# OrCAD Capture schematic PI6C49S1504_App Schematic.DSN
size Custom; title: PI6C49S1504 Application Circuit; rev: 1.0; note: Diodes Inc. Clock IC Application Engineering
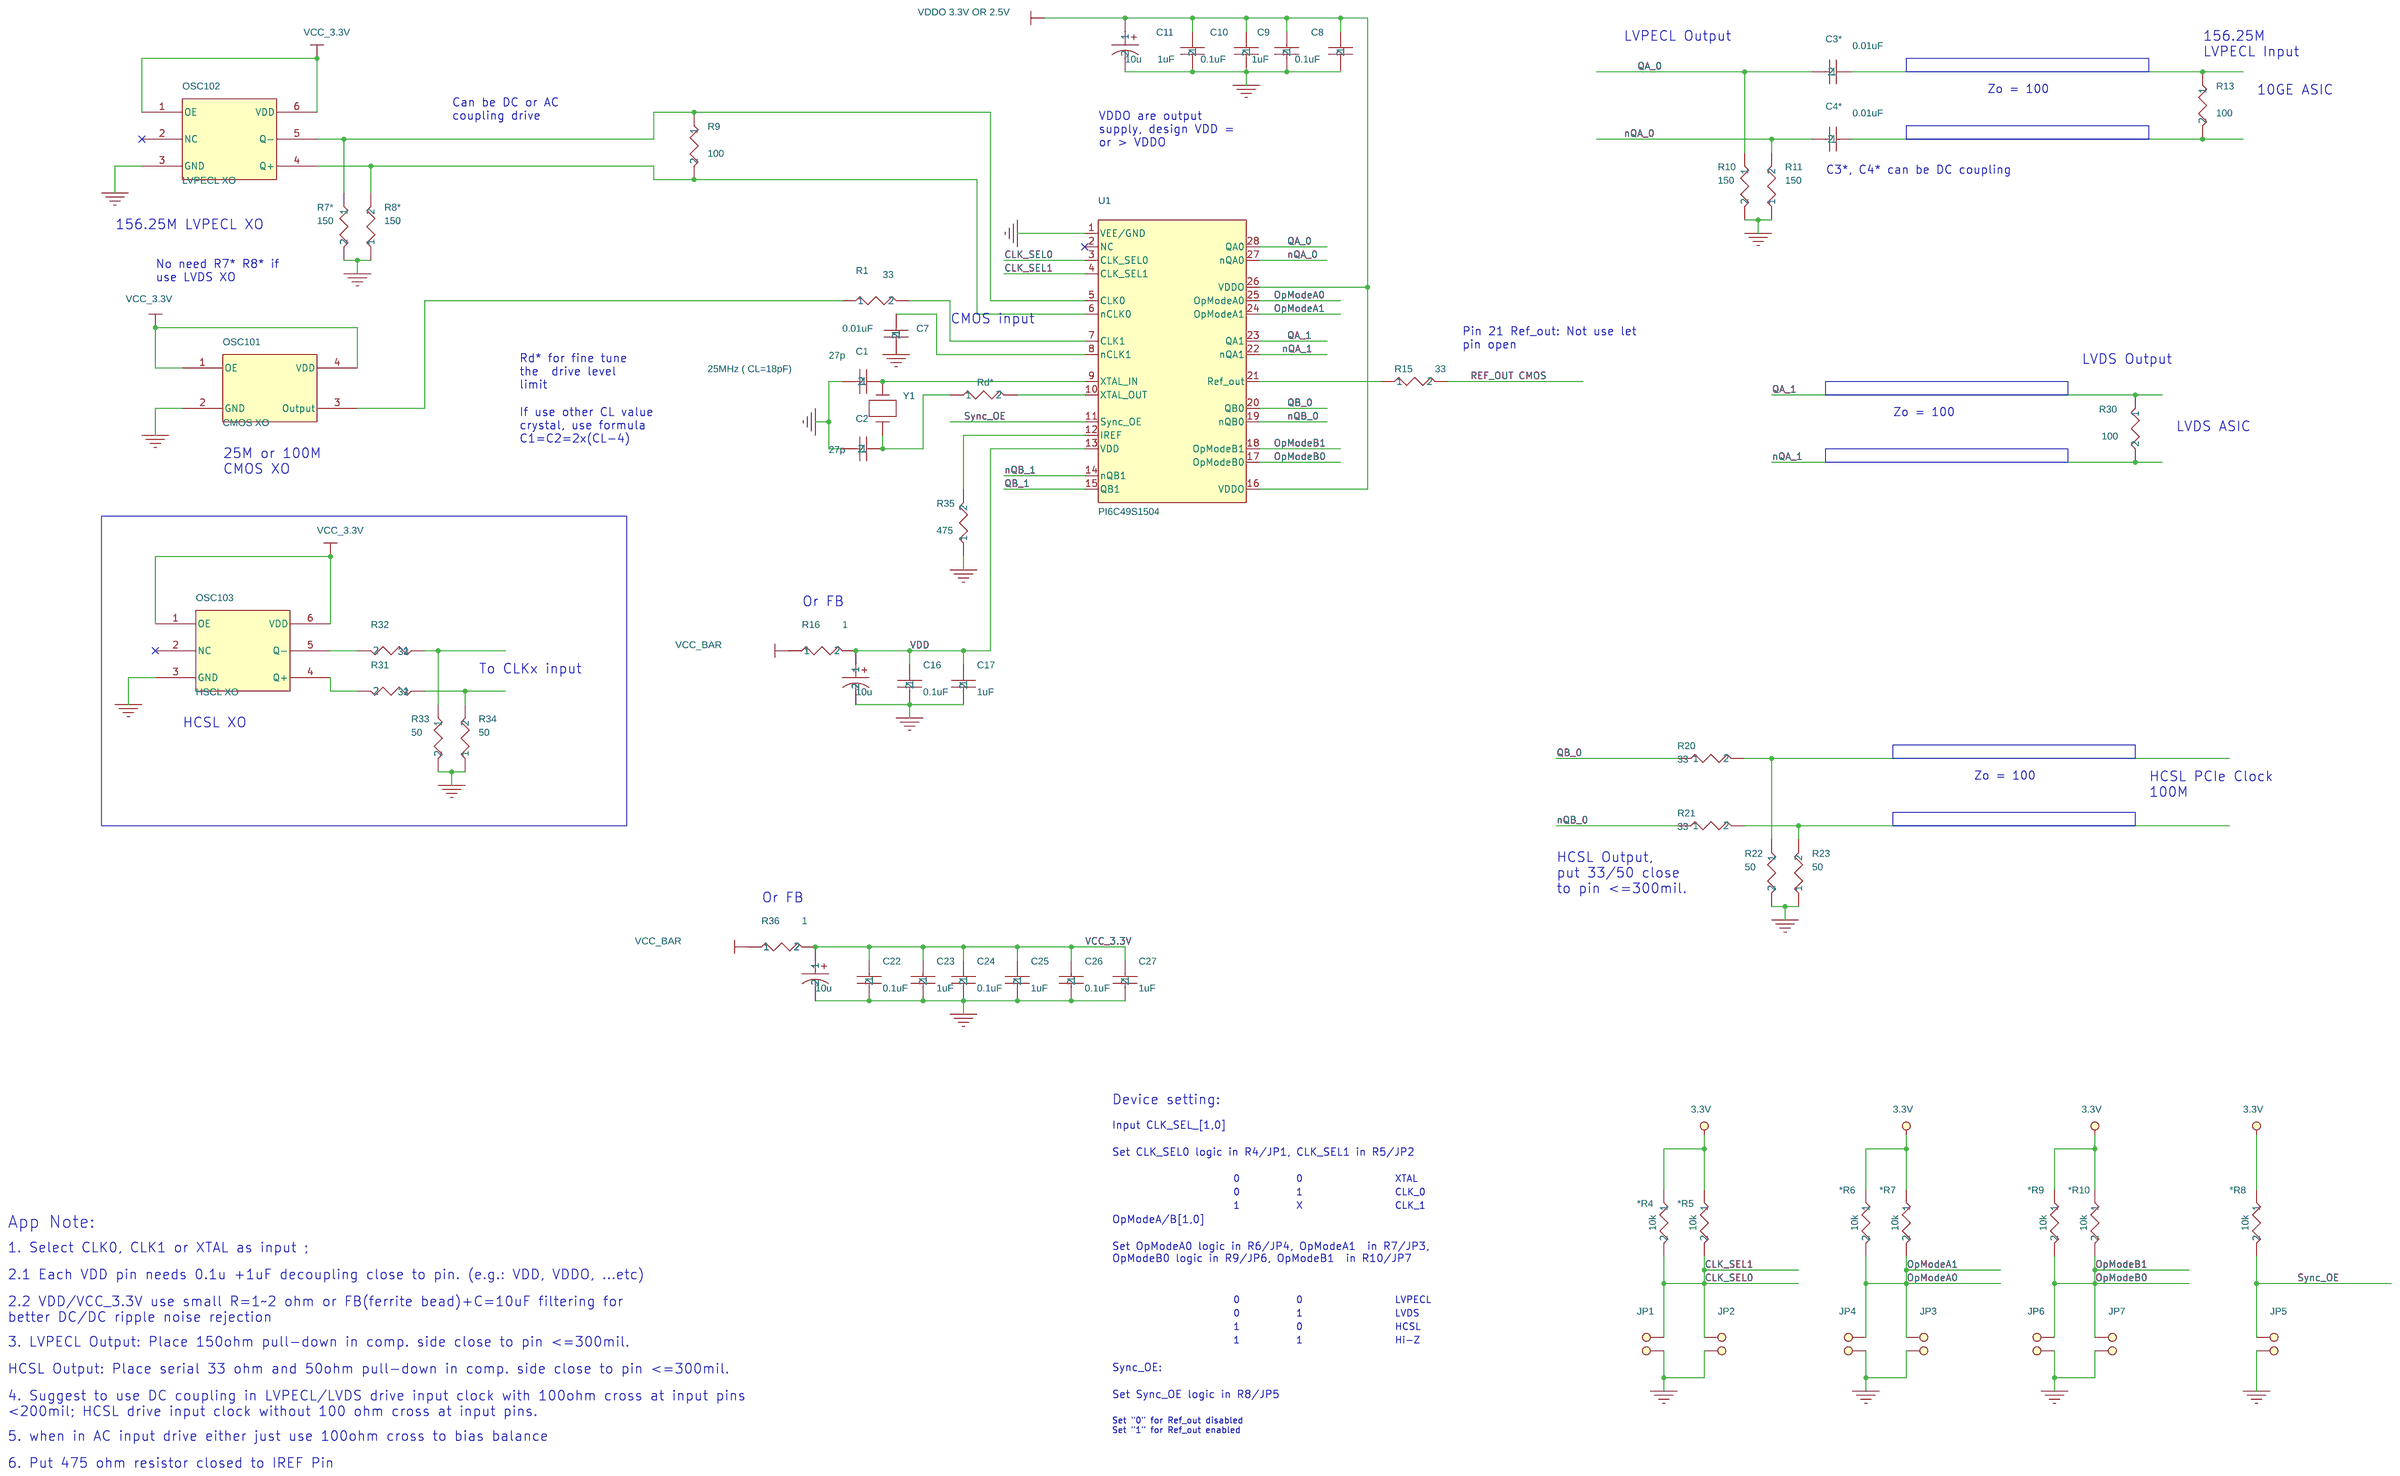
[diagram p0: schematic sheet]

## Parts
*R4  10k  [R_0402]
*R5  10k  [R_0402]
*R6  10k  [R_0402]
*R7  10k  [R_0402]
*R8  10k  [R_0402]
*R9  10k  [R_0402]
*R10  10k  [R_0402]
C1  27p  [CC_0402]
C2  27p  [CC_0402]
C3*  0.01uF  [CC_0402]
C4*  0.01uF  [CC_0402]
C7  0.01uF  [CC_0402]
C8  0.1uF  [CC_0402]
C9  1uF  [CC_0402]
C10  0.1uF  [CC_0402]
C11  1uF  [CC_0402]
C16  0.1uF  [CC_0402]
C17  1uF  [CC_0402]
C22  0.1uF  [CC_0402]
C23  1uF  [CC_0402]
C24  0.1uF  [CC_0402]
C25  1uF  [CC_0402]
C26  0.1uF  [CC_0402]
C27  1uF  [CC_0402]
EC1  10u  [CAP1000UF]
EC2  10u  [CAP1000UF]
EC3  10u  [CAP1000UF]
JP1  2PIN HEADER  [SIP\2P]
JP2  2PIN HEADER  [SIP\2P]
JP3  2PIN HEADER  [SIP\2P]
JP4  2PIN HEADER  [SIP\2P]
JP5  2PIN HEADER  [SIP\2P]
JP6  2PIN HEADER  [SIP\2P]
JP7  2PIN HEADER  [SIP\2P]
OSC101  CMOS XO  [CYRSTAL-3_2X2_5MM]
OSC102  LVPECL XO  [OSC-SMD-6P-32X25]
OSC103  HSCL XO  [OSC-SMD-6P-32X25]
R1  33  [R_0402]
R7*  150  [R_0402]
R8*  150  [R_0402]
R9  100  [R_0402]
R10  150  [R_0402]
R11  150  [R_0402]
R13  100  [R_0402]
R15  33  [R_0402]
R16  1  [R_0402]
R20  33  [R_0402]
R21  33  [R_0402]
R22  50  [R_0402]
R23  50  [R_0402]
R30  100  [R_0402]
R31  33  [R_0402]
R32  33  [R_0402]
R33  50  [R_0402]
R34  50  [R_0402]
R35  475  [R_0402]
R36  1  [R_0402]
Rd*  33  [R_0402]
U1  PI6C49S1504  [TQFN48]
Y1  25MHz ( CL=18pF)  [CRYSTAL SMD]

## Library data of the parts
*R4 = R_0402_22
*R5 = R_0402_13
*R6 = R_0402_17
*R7 = R_0402_16
*R8 = R_0402_20
*R9 = R_0402_27
*R10 = R_0402_25
C1 = C_10n_0402_15
C2 = C_10n_0402_4
C3* = C_10n_0402_5
C4* = C_10n_0402_13
C7 = C_10n_0402_7
C8 = C_10n_0402_11
C9 = C_10n_0402_9
C10 = C_10n_0402_6
C11 = C_10n_0402_16
C16 = C_10n_0402_14
C17 = C_10n_0402_12
C22 = C_10n_0402_3
C23 = C_10n_0402_2
C24 = C_10n_0402_1
C25 = C_10n_0402
C26 = C_10n_0402_10
C27 = C_10n_0402_8
EC1 = C_alum_1000u_1
EC2 = C_alum_1000u_2
EC3 = C_alum_1000u
JP1-JP7 = 2PIN_HEADER
OSC101 = UX3AA00003_0
OSC102 OSC103 = OSC_4P_HST_2
R1 = R_0402_5
R7* = R_0402_8
R8* = R_0402_21
R9 = R_0402
R10 = R_0402_11
R11 = R_0402_12
R13 = R_0402_7
R15 = R_0402_3
R16 = R_0402_2
R20 = R_0402_14
R21 = R_0402_10
R22 = R_0402_9
R23 = R_0402_6
R30 = R_0402_23
R31 = R_0402_26
R32 = R_0402_1
R33 = R_0402_19
R34 = R_0402_18
R35 = R_0402_4
R36 = R_0402_15
Rd* = R_0402_24
U1 = PI6C49S1510ZDE@TQFN48_4
Y1 = Crystal_SMD

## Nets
3.3V: *R4.1 *R5.1 *R6.1 *R7.1 *R8.1 *R9.1 *R10.1
GND: C1.2 C2.2 C7.2 C8.2 C9.2 C10.2 C11.2 C16.2 C17.2 C22.2 C23.2 C24.2 C25.2 C26.2 C27.2 EC1.2 EC2.2 EC3.2 JP1.1 JP2.1 JP3.1 JP4.1 JP5.1 JP6.1 JP7.1 OSC101.2(GND) OSC102.3(GND) OSC103.3(GND) R7*.1 R8*.2 R10.1 R11.2 R22.1 R23.2 R33.1 R34.2 R35.1 U1.1(VEE/GND)
VCC3.3V: R36.1
VCC_3.3V: C22.1 C23.1 C24.1 C25.1 C26.1 C27.1 EC2.1 OSC101.1(OE) OSC101.4(VDD) OSC102.1(OE) OSC102.6(VDD) OSC103.1(OE) OSC103.6(VDD) R36.2
VDD: C16.1 C17.1 EC1.1 R16.2 U1.13(VDD)
VDD3.3V or 2.5V: R16.1
VDDO 3.3V or 2.5V: C8.1 C9.1 C10.1 C11.1 EC3.1 U1.16(VDDO) U1.26(VDDO)
CLK_SEL0: *R4.2 JP1.2 U1.3(CLK_SEL0)
CLK_SEL1: *R5.2 JP2.2 U1.4(CLK_SEL1)
nQA_0: C4*.2 R10.2 U1.27(nQA0)
nQA_1: R30.2 U1.22(nQA1)
nQB_0: R21.1 U1.19(nQB0)
nQB_1: U1.14(nQB1)
OpModeA0: *R6.2 JP4.2 U1.25(OpModeA0)
OpModeA1: *R7.2 JP3.2 U1.24(OpModeA1)
OpModeB0: *R9.2 JP6.2 U1.17(OpModeB0)
OpModeB1: *R10.2 JP7.2 U1.18(OpModeB1)
QA_0: C3*.2 R11.1 U1.28(QA0)
QA_1: R30.1 U1.23(QA1)
QB_0: R20.1 U1.20(QB0)
QB_1: U1.15(QB1)
REF_OUT CMOS: R15.2
Sync_OE: *R8.2 JP5.2 U1.11(Sync_OE)
N3694759: OSC102.5(Q-) R8*.1 R9.1 U1.5(CLK0)
N3694767: OSC102.4(Q+) R7*.2 R9.2 U1.6(nCLK0)
N3697571: C1.1 U1.9(XTAL_IN) Y1.2
N3697589: Rd*.2 U1.10(XTAL_OUT)
N3697593: R1.2 U1.7(CLK1)
N3697653: C2.1 Rd*.1 Y1.1
N3697705: C7.1 U1.8(nCLK1)
N3697917: R15.1 U1.21(Ref_out)
N3698990: OSC103.4(Q+) R31.2
N3699088: R32.1 R34.1
N3699124: OSC103.5(Q-) R32.2
N3699152: R31.1 R33.2
N3699340: OSC101.3(Output) R1.1
N3699588: R35.2 U1.12(IREF)
N3706733: R20.2 R23.1
N3706737: R21.2 R22.2
N3707123: C3*.1 R13.1
N3707137: C4*.1 R13.2

Not connected (* = marked no-connect by the designer): OSC102 2(NC)*; OSC103 2(NC)*; U1 2(NC)*

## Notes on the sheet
- LVPECL Output
- 156.25M
  LVPECL Input
- Zo = 100
- 10GE ASIC
- Can be DC or AC
  coupling drive
- VDDO are output
  supply, design VDD =
  or > VDDO
- C3*, C4* can be DC coupling
- 156.25M LVPECL XO
- No need R7* R8* if
  use LVDS XO
- CMOS input
- Pin 21 Ref_out: Not use let
  pin open
- Rd* for fine tune
  the  drive level
  limit
- LVDS Output
- If use other CL value
  crystal, use formula
  C1=C2=2x(CL-4)
- Zo = 100
- LVDS ASIC
- 25M or 100M
  CMOS XO
- Or FB
- To CLKx input
- HCSL XO
- Zo = 100
- HCSL PCIe Clock
  100M
- HCSL Output,
  put 33/50 close
  to pin <=300mil.
- Or FB
- Device setting:
- Input CLK_SEL_[1,0]
- Set CLK_SEL0 logic in R4/JP1, CLK_SEL1 in R5/JP2
- 0           0
- XTAL
- 0           1
- 1           X
- CLK_0
- CLK_1
- App Note:
- OpModeA/B[1,0]
- 1. Select CLK0, CLK1 or XTAL as input ;
- Set OpModeA0 logic in R6/JP4, OpModeA1  in R7/JP3,
  OpModeB0 logic in R9/JP6, OpModeB1  in R10/JP7
- 2.1 Each VDD pin needs 0.1u +1uF decoupling close to pin. (e.g.: VDD, VDDO, ...etc)
- 2.2 VDD/VCC_3.3V use small R=1~2 ohm or FB(ferrite bead)+C=10uF filtering for
  better DC/DC ripple noise rejection
- 0           0
- LVPECL
- 0           1
- LVDS
- 1           0
- HCSL
- 3. LVPECL Output: Place 150ohm pull-down in comp. side close to pin <=300mil.
- 1           1
- Hi-Z
- HCSL Output: Place serial 33 ohm and 50ohm pull-down in comp. side close to pin <=300mil.
- Sync_OE:
- 4. Suggest to use DC coupling in LVPECL/LVDS drive input clock with 100ohm cross at input pins
  <200mil; HCSL drive input clock without 100 ohm cross at input pins.
- Set Sync_OE logic in R8/JP5
- Set "0" for Ref_out disabled
  Set "1" for Ref_out enabled
- 5. when in AC input drive either just use 100ohm cross to bias balance
- 6. Put 475 ohm resistor closed to IREF Pin
